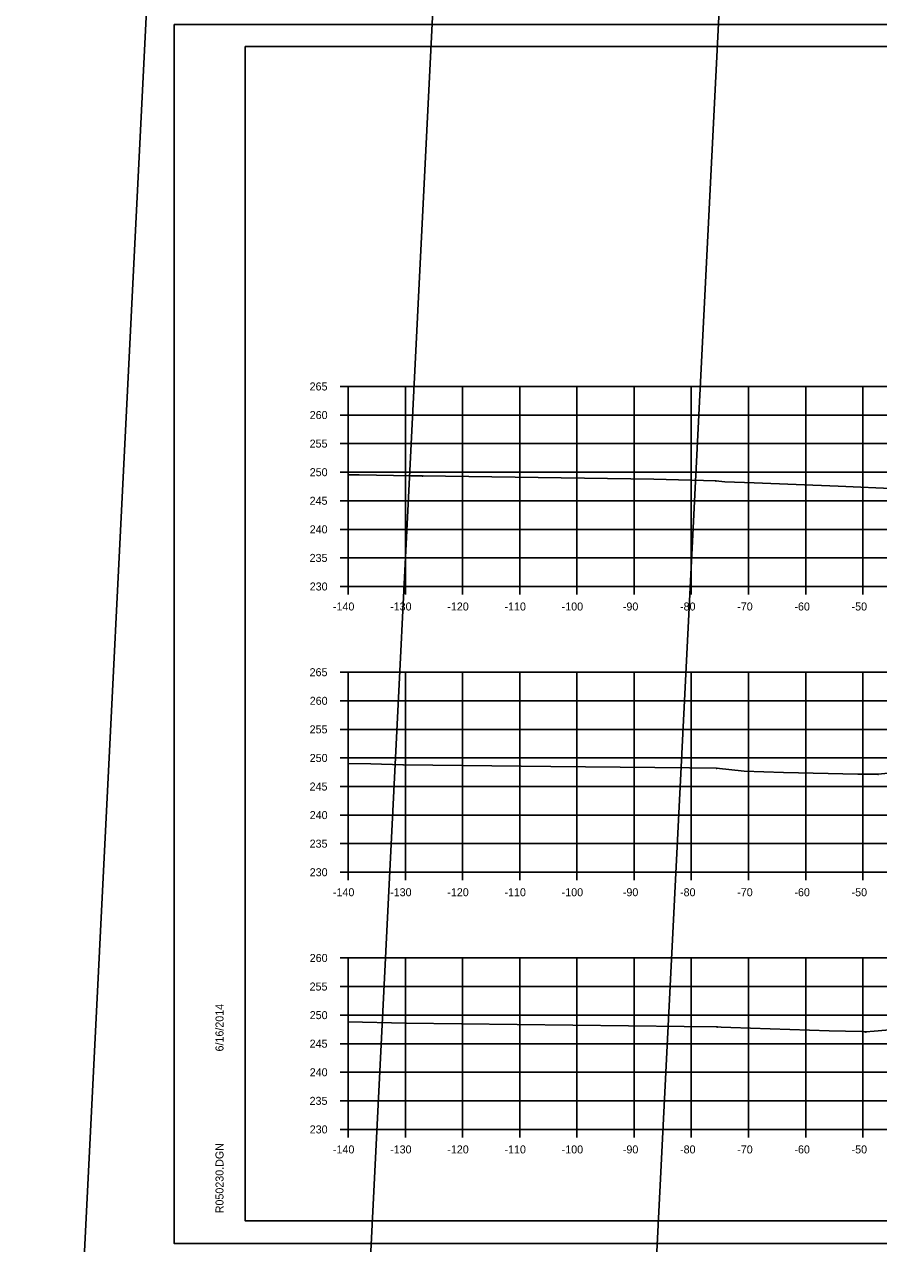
# Model space of a CAD drawing. Extents: x 1300404 to 1323571, y 234004 to 252077.
# Drawn here: x 1315520.7 to 1315670, y 242341.8 to 242555.1 of the extents above; entities that cross this region are included whole.
import ezdxf

# ---------------------------------------------------------------- set-up
doc = ezdxf.new("R2010")
doc.units = 0
for name, color, linetype in [('Default', 7, 'Continuous'), ('R_Axis', 7, 'Continuous'), ('R_Axis Annot', 7, 'Continuous'), ('R_Border', 7, 'Continuous'), ('R_Draft', 7, 'Continuous'), ('R_Exist Surface', 7, 'Continuous'), ('R_Floodway', 7, 'Continuous'), ('R_Grid', 7, 'Continuous'), ('R_No Plot', 7, 'Continuous')]:
    doc.layers.add(name, color=color, linetype=linetype)

msp = doc.modelspace()

# ---------------------------------------------------------------- linework, layer by layer
at = {"layer": 'Default'}
for p, q in [((1315559.28, 242551.24), (1315875.46, 242551.24)), ((1315559.28, 242345.78), (1315559.28, 242551.24)), ((1315875.46, 242345.78), (1315559.28, 242345.78))]:
    msp.add_line(p, q, dxfattribs=at)
at = {"layer": 'R_Axis'}
for p, q in [((1315575.88, 242491.78), (1315577.28, 242491.78)), ((1315577.28, 242456.78), (1315577.28, 242491.78)), ((1315575.88, 242486.78), (1315577.28, 242486.78)), ((1315575.88, 242481.78), (1315577.28, 242481.78)), ((1315575.88, 242476.78), (1315577.28, 242476.78)), ((1315575.88, 242471.78), (1315577.28, 242471.78)), ((1315575.88, 242466.78), (1315577.28, 242466.78)), ((1315575.88, 242461.78), (1315577.28, 242461.78)), ((1315575.88, 242456.78), (1315577.28, 242456.78)), ((1315577.28, 242456.78), (1315857.28, 242456.78)), ((1315577.28, 242455.38), (1315577.28, 242456.78)), ((1315587.28, 242455.38), (1315587.28, 242456.78)), ((1315597.28, 242455.38), (1315597.28, 242456.78)), ((1315607.28, 242455.38), (1315607.28, 242456.78)), ((1315617.28, 242455.38), (1315617.28, 242456.78)), ((1315627.28, 242455.38), (1315627.28, 242456.78)), ((1315637.28, 242455.38), (1315637.28, 242456.78)), ((1315647.28, 242455.38), (1315647.28, 242456.78)), ((1315657.28, 242455.38), (1315657.28, 242456.78)), ((1315667.28, 242455.38), (1315667.28, 242456.78)), ((1315575.88, 242441.78), (1315577.28, 242441.78)), ((1315577.28, 242406.78), (1315577.28, 242441.78)), ((1315575.88, 242436.78), (1315577.28, 242436.78)), ((1315575.88, 242431.78), (1315577.28, 242431.78)), ((1315575.88, 242426.78), (1315577.28, 242426.78)), ((1315575.88, 242421.78), (1315577.28, 242421.78)), ((1315575.88, 242416.78), (1315577.28, 242416.78)), ((1315575.88, 242411.78), (1315577.28, 242411.78)), ((1315575.88, 242406.78), (1315577.28, 242406.78)), ((1315577.28, 242406.78), (1315857.28, 242406.78)), ((1315577.28, 242405.38), (1315577.28, 242406.78)), ((1315587.28, 242405.38), (1315587.28, 242406.78)), ((1315597.28, 242405.38), (1315597.28, 242406.78)), ((1315607.28, 242405.38), (1315607.28, 242406.78)), ((1315617.28, 242405.38), (1315617.28, 242406.78)), ((1315627.28, 242405.38), (1315627.28, 242406.78)), ((1315637.28, 242405.38), (1315637.28, 242406.78)), ((1315647.28, 242405.38), (1315647.28, 242406.78)), ((1315657.28, 242405.38), (1315657.28, 242406.78)), ((1315667.28, 242405.38), (1315667.28, 242406.78)), ((1315575.88, 242391.78), (1315577.28, 242391.78)), ((1315577.28, 242361.78), (1315577.28, 242391.78)), ((1315575.88, 242386.78), (1315577.28, 242386.78)), ((1315575.88, 242381.78), (1315577.28, 242381.78)), ((1315575.88, 242376.78), (1315577.28, 242376.78)), ((1315575.88, 242371.78), (1315577.28, 242371.78)), ((1315575.88, 242366.78), (1315577.28, 242366.78)), ((1315575.88, 242361.78), (1315577.28, 242361.78)), ((1315577.28, 242361.78), (1315857.28, 242361.78)), ((1315577.28, 242360.38), (1315577.28, 242361.78)), ((1315587.28, 242360.38), (1315587.28, 242361.78)), ((1315597.28, 242360.38), (1315597.28, 242361.78)), ((1315607.28, 242360.38), (1315607.28, 242361.78)), ((1315617.28, 242360.38), (1315617.28, 242361.78)), ((1315627.28, 242360.38), (1315627.28, 242361.78)), ((1315637.28, 242360.38), (1315637.28, 242361.78)), ((1315647.28, 242360.38), (1315647.28, 242361.78)), ((1315657.28, 242360.38), (1315657.28, 242361.78)), ((1315667.28, 242360.38), (1315667.28, 242361.78))]:
    msp.add_line(p, q, dxfattribs=at)
at = {"layer": 'R_Border'}
msp.add_line((1315559.28, 242345.78), (1315559.28, 242345.78), dxfattribs=at)
at = {"layer": 'R_Draft'}
for points in [[(1315590.26, 242476.21), (1315590.31, 242476.11), (1315590.21, 242476.11)], [(1315641.58, 242475.33), (1315641.63, 242475.23), (1315641.53, 242475.23)], [(1315586.91, 242425.65), (1315586.96, 242425.55), (1315586.86, 242425.55)], [(1315641.68, 242425.04), (1315641.73, 242424.94), (1315641.63, 242424.94)], [(1315669.96, 242424), (1315670.01, 242423.9), (1315669.91, 242423.9)], [(1315587.36, 242380.4), (1315587.41, 242380.3), (1315587.31, 242380.3)], [(1315641.8, 242379.76), (1315641.85, 242379.66), (1315641.75, 242379.66)], [(1315667.81, 242378.92), (1315667.86, 242378.82), (1315667.76, 242378.82)]]:
    msp.add_lwpolyline(points, close=True, dxfattribs=at)
at = {"layer": 'R_Exist Surface'}
for points in [[(1315577.28, 242476.33), (1315579.18, 242476.3), (1315588.24, 242476.17), (1315590.26, 242476.16), (1315630.72, 242475.53), (1315641.58, 242475.28), (1315643.13, 242475.11), (1315648.27, 242474.93), (1315662.94, 242474.31), (1315673.51, 242473.85)], [(1315577.28, 242425.82), (1315581.22, 242425.73), (1315586.91, 242425.6), (1315612.74, 242425.31), (1315636.96, 242425.07), (1315641.68, 242424.99), (1315646.5, 242424.45), (1315653.38, 242424.26), (1315666.42, 242423.94), (1315669.96, 242423.95), (1315672.81, 242424.21)], [(1315577.28, 242380.59), (1315587.36, 242380.35), (1315636.02, 242379.77), (1315641.8, 242379.71), (1315642.52, 242379.65), (1315644.21, 242379.63), (1315661.38, 242379.02), (1315667.1, 242378.89), (1315667.56, 242378.87), (1315667.81, 242378.87), (1315669.27, 242378.99), (1315676.72, 242379.64)]]:
    msp.add_lwpolyline(points, dxfattribs=at)
at = {"layer": 'R_Floodway'}
for p, q in [((1315622.37, 242162.75), (1315664.37, 243001.24)), ((1315571.51, 242146.87), (1315613.29, 242980.93)), ((1315520.65, 242130.98), (1315562.21, 242960.62))]:
    msp.add_line(p, q, dxfattribs=at)
at = {"layer": 'R_Grid'}
for p, q in [((1315577.28, 242491.78), (1315857.28, 242491.78)), ((1315577.28, 242456.78), (1315577.28, 242491.78)), ((1315587.28, 242456.78), (1315587.28, 242491.78)), ((1315597.28, 242456.78), (1315597.28, 242491.78)), ((1315607.28, 242456.78), (1315607.28, 242491.78)), ((1315617.28, 242456.78), (1315617.28, 242491.78)), ((1315627.28, 242456.78), (1315627.28, 242491.78)), ((1315637.28, 242456.78), (1315637.28, 242491.78)), ((1315647.28, 242456.78), (1315647.28, 242491.78)), ((1315657.28, 242456.78), (1315657.28, 242491.78)), ((1315667.28, 242456.78), (1315667.28, 242491.78)), ((1315577.28, 242486.78), (1315857.28, 242486.78)), ((1315577.28, 242481.78), (1315857.28, 242481.78)), ((1315577.28, 242476.78), (1315857.28, 242476.78)), ((1315577.28, 242471.78), (1315857.28, 242471.78)), ((1315577.28, 242466.78), (1315857.28, 242466.78)), ((1315577.28, 242461.78), (1315857.28, 242461.78)), ((1315577.28, 242456.78), (1315857.28, 242456.78)), ((1315577.28, 242441.78), (1315857.28, 242441.78)), ((1315577.28, 242406.78), (1315577.28, 242441.78)), ((1315587.28, 242406.78), (1315587.28, 242441.78)), ((1315597.28, 242406.78), (1315597.28, 242441.78)), ((1315607.28, 242406.78), (1315607.28, 242441.78)), ((1315617.28, 242406.78), (1315617.28, 242441.78)), ((1315627.28, 242406.78), (1315627.28, 242441.78)), ((1315637.28, 242406.78), (1315637.28, 242441.78)), ((1315647.28, 242406.78), (1315647.28, 242441.78)), ((1315657.28, 242406.78), (1315657.28, 242441.78)), ((1315667.28, 242406.78), (1315667.28, 242441.78)), ((1315577.28, 242436.78), (1315857.28, 242436.78)), ((1315577.28, 242431.78), (1315857.28, 242431.78)), ((1315577.28, 242426.78), (1315857.28, 242426.78)), ((1315577.28, 242421.78), (1315857.28, 242421.78)), ((1315577.28, 242416.78), (1315857.28, 242416.78)), ((1315577.28, 242411.78), (1315857.28, 242411.78)), ((1315577.28, 242406.78), (1315857.28, 242406.78)), ((1315577.28, 242391.78), (1315857.28, 242391.78)), ((1315577.28, 242361.78), (1315577.28, 242391.78)), ((1315587.28, 242361.78), (1315587.28, 242391.78)), ((1315597.28, 242361.78), (1315597.28, 242391.78)), ((1315607.28, 242361.78), (1315607.28, 242391.78)), ((1315617.28, 242361.78), (1315617.28, 242391.78)), ((1315627.28, 242361.78), (1315627.28, 242391.78)), ((1315637.28, 242361.78), (1315637.28, 242391.78)), ((1315647.28, 242361.78), (1315647.28, 242391.78)), ((1315657.28, 242361.78), (1315657.28, 242391.78)), ((1315667.28, 242361.78), (1315667.28, 242391.78)), ((1315577.28, 242386.78), (1315857.28, 242386.78)), ((1315577.28, 242381.78), (1315857.28, 242381.78)), ((1315577.28, 242376.78), (1315857.28, 242376.78)), ((1315577.28, 242371.78), (1315857.28, 242371.78)), ((1315577.28, 242366.78), (1315857.28, 242366.78)), ((1315577.28, 242361.78), (1315857.28, 242361.78))]:
    msp.add_line(p, q, dxfattribs=at)
at = {"layer": 'R_No Plot'}
for p, q in [((1315546.87, 242555.14), (1315880.21, 242555.14)), ((1315546.87, 242341.8), (1315880.21, 242341.8))]:
    msp.add_line(p, q, dxfattribs=at)
for points in [[(1315546.87, 242555.14), (1315880.21, 242555.14), (1315880.21, 242341.8), (1315546.87, 242341.8)], [(1315793.2, 242551.24), (1315793.2, 242541.36), (1315828.93, 242541.36), (1315828.93, 242538.44), (1315852.13, 242538.44), (1315852.13, 242516.32), (1315875.46, 242516.32), (1315875.46, 242345.78), (1315559.28, 242345.78), (1315559.28, 242551.24)]]:
    msp.add_lwpolyline(points, close=True, dxfattribs=at)

# ---------------------------------------------------------------- texts
at = {"layer": 'R_Axis'}
for p in [(1315577.28, 242456.78), (1315577.28, 242406.78), (1315577.28, 242361.78)]:
    msp.add_text('-', height=0.0001, dxfattribs=at).set_placement(p)
at = {"layer": 'R_Axis Annot'}
for s, p in [('265', (1315570.53, 242491.08)), ('260', (1315570.55, 242486.08)), ('255', (1315570.53, 242481.08)), ('250', (1315570.55, 242476.08)), ('245', (1315570.53, 242471.08)), ('240', (1315570.55, 242466.08)), ('235', (1315570.53, 242461.08)), ('230', (1315570.55, 242456.08)), ('-140', (1315574.61, 242452.58)), ('-130', (1315584.61, 242452.58)), ('-120', (1315594.61, 242452.58)), ('-110', (1315604.61, 242452.58)), ('-100', (1315614.61, 242452.58)), ('-90', (1315625.31, 242452.58)), ('-80', (1315635.31, 242452.58)), ('-70', (1315645.31, 242452.58)), ('-60', (1315655.31, 242452.58)), ('-50', (1315665.31, 242452.58)), ('265', (1315570.53, 242441.08)), ('260', (1315570.55, 242436.08)), ('255', (1315570.53, 242431.08)), ('250', (1315570.55, 242426.08)), ('245', (1315570.53, 242421.08)), ('240', (1315570.55, 242416.08)), ('235', (1315570.53, 242411.08)), ('230', (1315570.55, 242406.08)), ('-140', (1315574.61, 242402.58)), ('-130', (1315584.61, 242402.58)), ('-120', (1315594.61, 242402.58)), ('-110', (1315604.61, 242402.58)), ('-100', (1315614.61, 242402.58)), ('-90', (1315625.31, 242402.58)), ('-80', (1315635.31, 242402.58)), ('-70', (1315645.31, 242402.58)), ('-60', (1315655.31, 242402.58)), ('-50', (1315665.31, 242402.58)), ('260', (1315570.55, 242391.08)), ('255', (1315570.53, 242386.08)), ('250', (1315570.55, 242381.08)), ('245', (1315570.53, 242376.08)), ('240', (1315570.55, 242371.08)), ('235', (1315570.53, 242366.08)), ('230', (1315570.55, 242361.08)), ('-140', (1315574.61, 242357.58)), ('-130', (1315584.61, 242357.58)), ('-120', (1315594.61, 242357.58)), ('-110', (1315604.61, 242357.58)), ('-100', (1315614.61, 242357.58)), ('-90', (1315625.31, 242357.58)), ('-80', (1315635.31, 242357.58)), ('-70', (1315645.31, 242357.58)), ('-60', (1315655.31, 242357.58)), ('-50', (1315665.31, 242357.58))]:
    msp.add_text(s, height=1.4, dxfattribs=at).set_placement(p)
at = {"layer": 'R_Border'}
for s, p in [('6/16/2014', (1315555.47, 242375.42)), ('R050230.DGN', (1315555.47, 242347.11))]:
    msp.add_text(s, height=1.4, rotation=90, dxfattribs=at).set_placement(p)

doc.saveas('drawing.dxf')
